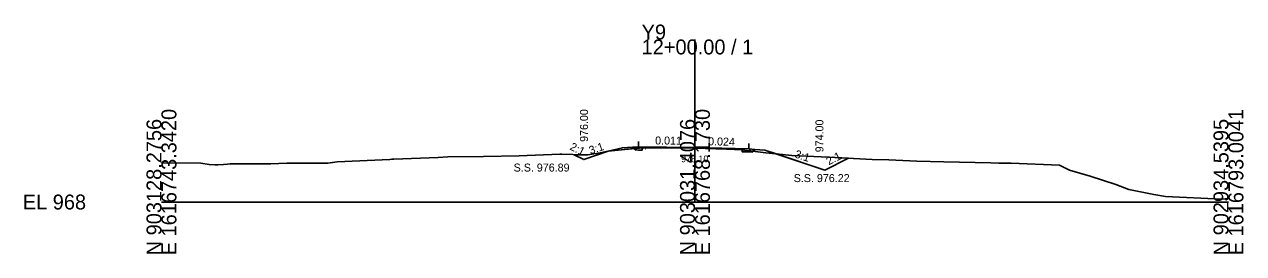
# Model space of a CAD drawing. Extents: x -26 to 1403, y -10 to 3021.
# Drawn here: x -25.7 to 202.8, y 1990.3 to 2033.4 of the extents above; entities that cross this region are included whole.
import ezdxf

# ---------------------------------------------------------------- set-up
doc = ezdxf.new("R2010")
doc.units = 0
for name, color, linetype in [('Default', 7, 'Continuous'), ('Exist Cross Section Cell', 7, 'Continuous'), ('Exist XS Center Line Elevation Label', 7, 'Continuous'), ('Exist XS Ground Line', 7, 'Continuous'), ('Prop XS Ditch Slope Text', 7, 'Continuous'), ('Prop XS Dump Level', 7, 'Continuous'), ('Prop XS Earthwork Shape', 7, 'Continuous'), ('Prop XS EOT Tick Mark', 7, 'Continuous'), ('Prop XS Finish Grade', 7, 'Continuous'), ('Prop XS Finish Grade Earthwork', 7, 'Continuous'), ('Prop XS Finish Grade Pavement', 7, 'Continuous'), ('Prop XS Pvmt Edge Slope', 7, 'Continuous'), ('Prop XS SE Text', 7, 'Continuous'), ('Prop XS Subgrade Earthwork', 7, 'Continuous')]:
    doc.layers.add(name, color=color, linetype=linetype)

msp = doc.modelspace()

# ---------------------------------------------------------------- linework, layer by layer
at = {"layer": 'Default'}
msp.add_line((99.94, 2010.1), (90.11, 2010.17), dxfattribs=at)
at = {"layer": 'Exist Cross Section Cell'}
for p, q in [((100, 2000), (100, 2030.51)), ((0, 2000), (100, 2000)), ((100, 2000), (200, 2000))]:
    msp.add_line(p, q, dxfattribs=at)
at = {"layer": 'Exist XS Ground Line'}
for p, q in [((67.03, 2008.69), (74.7, 2008.99)), ((74.7, 2008.99), (75.05, 2008.96)), ((75.05, 2008.96), (79.16, 2008.83)), ((79.16, 2008.83), (79.91, 2008.84)), ((79.91, 2008.84), (81.06, 2009.05)), ((81.06, 2009.05), (81.56, 2009.14)), ((81.56, 2009.14), (82.83, 2009.38)), ((82.83, 2009.38), (83.68, 2009.53)), ((83.68, 2009.53), (90.11, 2010.17)), ((90.11, 2010.17), (99.94, 2010.1)), ((99.94, 2010.1), (105.94, 2009.9)), ((105.94, 2009.9), (108.82, 2009.77)), ((108.82, 2009.77), (113.27, 2009.25)), ((113.27, 2009.25), (118.15, 2008.74)), ((0, 2007.37), (7.37, 2007.3)), ((7.37, 2007.3), (8.94, 2007.07)), ((8.94, 2007.07), (9.98, 2006.96)), ((9.98, 2006.96), (10.59, 2006.99)), ((10.59, 2006.99), (11.63, 2007.04)), ((11.63, 2007.04), (12.39, 2007.12)), ((12.39, 2007.12), (12.91, 2007.14)), ((12.91, 2007.14), (20.48, 2007.19)), ((20.48, 2007.19), (23.52, 2007.3)), ((23.52, 2007.3), (24.62, 2007.31)), ((24.62, 2007.31), (31.19, 2007.31)), ((31.19, 2007.31), (32.95, 2007.53)), ((32.95, 2007.53), (42.81, 2008.01)), ((42.81, 2008.01), (43.16, 2008.03)), ((43.16, 2008.03), (43.54, 2008.05)), ((43.54, 2008.05), (51.86, 2008.38)), ((51.86, 2008.38), (53.68, 2008.46)), ((53.68, 2008.46), (60.39, 2008.56)), ((60.39, 2008.56), (67.03, 2008.69)), ((118.15, 2008.74), (125.06, 2008.43)), ((125.06, 2008.43), (133.23, 2007.96)), ((133.23, 2007.96), (136.34, 2007.9)), ((136.34, 2007.9), (141.58, 2007.69)), ((141.58, 2007.69), (146.66, 2007.53)), ((146.66, 2007.53), (155.47, 2007.37)), ((155.47, 2007.37), (156.98, 2007.32)), ((156.98, 2007.32), (159.24, 2007.31)), ((159.24, 2007.31), (168.35, 2006.93)), ((168.35, 2006.93), (170.2, 2006.01)), ((170.2, 2006.01), (174.08, 2004.88)), ((174.08, 2004.88), (178.88, 2003.29)), ((178.88, 2003.29), (181.3, 2002.35)), ((181.3, 2002.35), (186.02, 2001.44)), ((186.02, 2001.44), (188.2, 2001.06)), ((188.2, 2001.06), (198.78, 2000.56)), ((198.78, 2000.56), (200, 2000.67))]:
    msp.add_line(p, q, dxfattribs=at)
at = {"layer": 'Prop XS Dump Level'}
for p, q in [((89.4, 2010.34), (100, 2010.22)), ((100, 2010.22), (110.12, 2009.98))]:
    msp.add_line(p, q, dxfattribs=at)
at = {"layer": 'Prop XS Earthwork Shape'}
for points in [[(77.33, 2008.89), (79.16, 2008.83), (79.91, 2008.84), (81.06, 2009.05), (81.56, 2009.14), (82.83, 2009.38), (83.68, 2009.53), (83.76, 2009.54), (79.15, 2007.98)], [(83.76, 2009.54), (88.57, 2010.02), (88.3, 2010.29), (86.4, 2010.2)], [(88.57, 2010.02), (89.13, 2010.07), (88.83, 2009.77)], [(89.4, 2009.76), (88.83, 2009.77), (89.13, 2010.07), (90.11, 2010.17), (90.11, 2009.75)], [(110.12, 2009.4), (110.72, 2009.39), (110.53, 2009.57), (108.82, 2009.77), (108.82, 2009.43)], [(110.72, 2009.39), (110.87, 2009.53), (110.53, 2009.57)], [(111.23, 2009.89), (113.12, 2009.74), (115.2, 2009.05), (113.27, 2009.25), (110.87, 2009.53)], [(115.2, 2009.05), (118.15, 2008.74), (125.06, 2008.43), (128.78, 2008.22), (124.35, 2006)]]:
    msp.add_lwpolyline(points, close=True, dxfattribs=at)
at = {"layer": 'Prop XS EOT Tick Mark'}
for p, q in [((89.4, 2010.34), (89.4, 2011.34)), ((110.12, 2009.98), (110.12, 2010.98))]:
    msp.add_line(p, q, dxfattribs=at)
at = {"layer": 'Prop XS Finish Grade'}
for p, q in [((89.4, 2010.34), (88.3, 2010.29)), ((110.12, 2009.98), (111.23, 2009.89))]:
    msp.add_line(p, q, dxfattribs=at)
at = {"layer": 'Prop XS Finish Grade Earthwork'}
for p, q in [((79.15, 2007.98), (77.33, 2008.89)), ((79.15, 2007.98), (83.76, 2009.54)), ((86.4, 2010.2), (83.76, 2009.54)), ((88.3, 2010.29), (86.4, 2010.2)), ((111.23, 2009.89), (113.12, 2009.74)), ((113.12, 2009.74), (124.35, 2006)), ((128.78, 2008.22), (124.35, 2006))]:
    msp.add_line(p, q, dxfattribs=at)
at = {"layer": 'Prop XS Finish Grade Pavement'}
for p, q in [((89.4, 2010.34), (100, 2010.22)), ((100, 2010.22), (110.12, 2009.98))]:
    msp.add_line(p, q, dxfattribs=at)
at = {"layer": 'Prop XS Pvmt Edge Slope'}
for p, q in [((89.4, 2010.34), (88.83, 2009.77)), ((110.12, 2009.98), (110.72, 2009.39))]:
    msp.add_line(p, q, dxfattribs=at)
at = {"layer": 'Prop XS Subgrade Earthwork'}
for p, q in [((88.83, 2009.77), (88.3, 2010.29)), ((89.4, 2009.76), (88.83, 2009.77)), ((90.11, 2009.75), (89.4, 2009.76)), ((90.11, 2009.75), (90.11, 2010.17)), ((108.82, 2009.43), (108.82, 2009.77)), ((108.82, 2009.43), (110.12, 2009.4)), ((110.12, 2009.4), (110.72, 2009.39)), ((110.72, 2009.39), (111.23, 2009.89))]:
    msp.add_line(p, q, dxfattribs=at)

# ---------------------------------------------------------------- texts
at = {"layer": 'Exist Cross Section Cell'}
for s, p in [('Y9', (90, 2030.51)), ('12+00.00 / 1', (90, 2027.71)), ('EL 968', (-26, 1998.6))]:
    msp.add_text(s, height=2.8, dxfattribs=at).set_placement(p)
for s, p in [('E 1616743.3420', (2.8, 1990)), ('E 1616768.1730', (102.8, 1990)), ('E 1616793.0041', (202.8, 1990)), ('N 903128.2756', (0, 1990)), ('N 903031.4076', (100, 1990)), ('N 902934.5395', (200, 1990))]:
    msp.add_text(s, height=2.8, rotation=90, dxfattribs=at).set_placement(p)
at = {"layer": 'Exist XS Center Line Elevation Label'}
msp.add_text('978.10', height=1.25, dxfattribs=at).set_placement((97.4, 2007.47))
at = {"layer": 'Prop XS Ditch Slope Text'}
for s, rotation, p in [('976.00', 90, (79.95, 2011.29)), ('974.00', 90, (124.08, 2009.34)), ('2:1', 333.4349, (76.41, 2009.91)), ('3:1', 18.4349, (80.43, 2008.93)), ('3:1', 341.5651, (118.58, 2008.4)), ('2:1', 26.5651, (125.07, 2006.89))]:
    msp.add_text(s, height=1.5, rotation=rotation, dxfattribs=at).set_placement(p)
for s, p in [('S.S. 976.89', (66.01, 2005.72)), ('S.S. 976.22', (118.51, 2003.74))]:
    msp.add_text(s, height=1.5, dxfattribs=at).set_placement(p)
at = {"layer": 'Prop XS Dump Level'}
for s, height, p in [('Case1', 0.04, (86.4, 2010.16)), ('Eop', 0.3, (90.11, 2009.87)), ('Eop', 0.3, (108.82, 2009.47)), ('Case1', 0.04, (113.12, 2009.7))]:
    msp.add_text(s, height=height, dxfattribs=at).set_placement(p)
at = {"layer": 'Prop XS SE Text'}
for s, rotation, p in [('0.011', 359.3455, (92.53, 2010.81)), ('0.024', 358.6494, (102.45, 2010.66))]:
    msp.add_text(s, height=1.5, rotation=rotation, dxfattribs=at).set_placement(p)

doc.saveas('drawing.dxf')
